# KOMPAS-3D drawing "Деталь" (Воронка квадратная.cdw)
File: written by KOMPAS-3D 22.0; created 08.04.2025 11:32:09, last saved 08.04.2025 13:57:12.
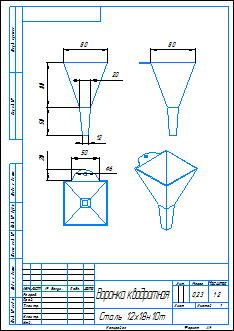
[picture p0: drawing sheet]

Sheet 1: A4, portrait

Document properties: Автор: Admin; Масса: 0.225513; Полное имя файла: Воронка квадратная.m3d

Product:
- Body: Тело 8
    Масса: 0.182888
- Body: Тело 9
    Масса: 0.182888
- Part/product: Деталь
    Масса: 0.225679

Title block, sheet 1: Наименование: Воронка квадратная; Материал: Сталь 12х18н10т; Масса: 0,23; Количество листов документа: 1; Форматы листов документа: A4; stored path: D:\28.11.2016\Абилимпикс\2025\Воронка квадратная.cdw

Views: Вид 1, Спереди, Проекционный вид 2, Проекционный вид 3, Проекционный вид 4
Referenced files in D:\28.11.2016\Абилимпикс\2025\: Воронка квадратная.m3d
Dimensions and other numbers on the sheet: 80; 50; 12; 20; 6; 1:2; 1; 0,23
